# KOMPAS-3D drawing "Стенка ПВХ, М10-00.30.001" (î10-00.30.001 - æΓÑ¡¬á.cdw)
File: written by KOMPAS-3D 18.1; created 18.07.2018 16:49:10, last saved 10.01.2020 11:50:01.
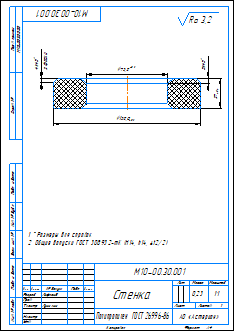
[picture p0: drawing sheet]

Sheet 1: A4, portrait

Document properties: Автор: Милов; Масса: 0.226956; Параметр неуказанной шероховатости: Ra 3,2; Полное имя файла: М10-00.30.001 - Стенка.m3d

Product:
- Part/product: Стенка ПВХ  | designation М10-00.30.001
    Материал: Полипропилен  ГОСТ 26996-86 (density 900 kg/m3)
    Масса: 0.266182
    Раздел спецификации: Детали
    Форматы листов документа: A4
- Part/product: Стенка  | designation М10-00.30.001
    Материал: Полипропилен  ГОСТ 26996-86 (density 900 kg/m3)
    Масса: 0.226956
    Раздел спецификации: Детали
    Форматы листов документа: A4
    source file: М10-00.30.001 - Стенка.cdw

Title block, sheet 1: Наименование: Стенка; designation: М10-00.30.001; Материал: Полипропилен  ГОСТ 26996-86; Масса: 0,23; scale: 1:1; Количество листов документа: 1; organisation: АО «Астерион»; Форматы листов документа: A4; stored path: Z:\Магна\Магна Ins\Магна ins 10\М10-00.00.000\3Д\М10-00.30.001 - Стенка.cdw; Разработал: Лифлянд; Т. контр.: Лучихин

Views: Вид 1, Местный разрез 1, Сверху, Проекционный вид 2
Referenced files in Z:\Магна\Магна Ins\Магна ins 10\М10-00.00.000\3Д\: М10-00.30.001 - Стенка.m3d
Referenced files in D:\Magna\Магна Ins\Магна ins 10\М10-00.00.000\3Д\: М10-00.30.001 - Стенка.m3d
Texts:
  Ra 3,2
Dimensions and other numbers on the sheet: 4; 2 фаски; 132,8; 27; 73,2; 5; 1:1; 1; 0,23

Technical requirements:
  *Размеры для справок.
  Общие допуски ГОСТ 30893.2-mK (H14, h14,  t2/2).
